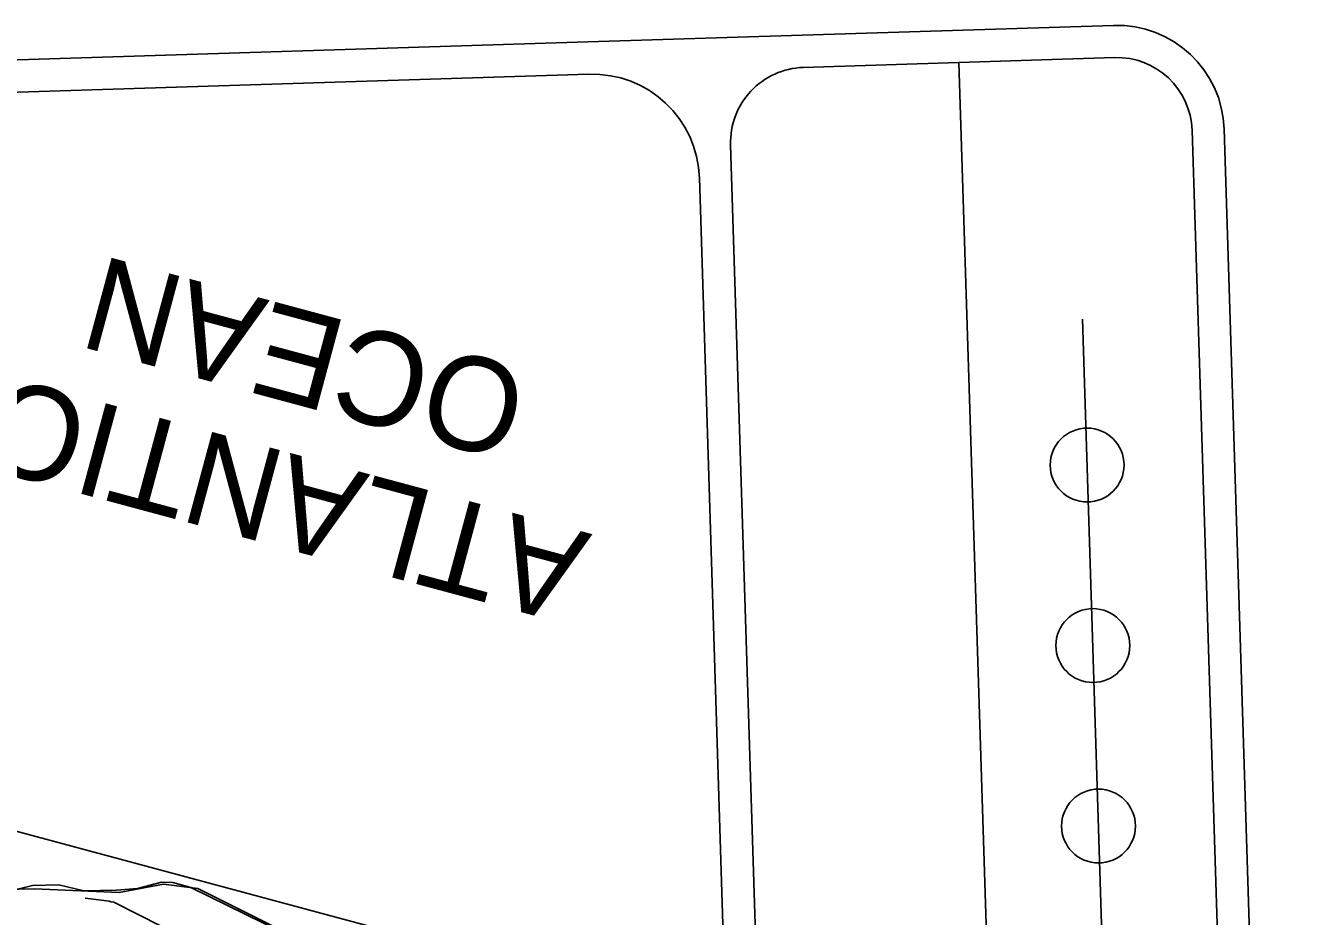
# Model space of a CAD drawing. Extents: x 2308163 to 2335412, y -96774 to 125428.
# Drawn here: x 2326312.3 to 2326608.3, y 123271.9 to 123479.6 of the extents above; entities that cross this region are included whole.
import ezdxf

# ---------------------------------------------------------------- set-up
doc = ezdxf.new("R2010")
doc.units = 0
for name, color, linetype in [('Default', 7, 'Continuous'), ('Old_Level_1', 7, 'Continuous'), ('Old_Level_21', 7, 'Continuous'), ('Old_Level_52', 7, 'Continuous'), ('Old_Level_60', 7, 'Continuous'), ('Old_Level_61', 7, 'Continuous'), ('Old_Level_63', 7, 'Continuous'), ('Prop Horizontal Alignment', 7, 'Continuous')]:
    doc.layers.add(name, color=color, linetype=linetype)

msp = doc.modelspace()

# ---------------------------------------------------------------- linework, layer by layer
at = {"layer": 'Default'}
for centre in [(2326559.69, 123377.11), (2326561.02, 123335.04), (2326562.34, 123292.96)]:
    msp.add_circle(centre, 8.61, dxfattribs=at)
at = {"layer": 'Old_Level_1'}
for p, q in [((2326443.34, 123475.72), (2326493.31, 123477.29)), ((2326493.31, 123477.29), (2326565.85, 123479.58)), ((2325949.48, 123460.16), (2326443.34, 123475.72)), ((2326493.55, 123469.8), (2326566.09, 123472.08)), ((2325949.72, 123452.66), (2326443.57, 123468.22)), ((2326547.56, 122907.89), (2326529.82, 123470.94)), ((2326600.77, 122927.08), (2326584.13, 123455.14)), ((2326493.25, 122923.69), (2326476.61, 123451.75)), ((2326485.52, 122930.95), (2326469.35, 123444.02))]:
    msp.add_line(p, q, dxfattribs=at)
msp.add_lwpolyline([(2326608.27, 122927.31), (2326591.63, 123455.38)], dxfattribs=at)
for centre, radius, start, end in [((2326566.64, 123454.59), 25, 1.8048, 91.8048), ((2326566.64, 123454.59), 17.5, 1.8048, 91.8048), ((2326444.36, 123443.23), 25, 1.8048, 91.8048), ((2326494.1, 123452.3), 17.5, 91.8048, 181.8048)]:
    msp.add_arc(centre, radius, start, end, dxfattribs=at)
at = {"layer": 'Old_Level_52'}
for points in [[(2326352.46, 123278.37), (2326344.49, 123279.39), (2326334.11, 123277.47), (2326314.41, 123278.3), (2326300.12, 123278.02), (2326291.22, 123283.57), (2326287.11, 123292.06), (2326280.06, 123298.67), (2326266.15, 123306.08), (2326194.23, 123339.67), (2326117.56, 123374.58), (2325996.97, 123429.09), (2325967.84, 123440.3), (2325941.49, 123450.31)], [(2326397.87, 123255.63), (2326352.46, 123278.37)]]:
    msp.add_lwpolyline(points, dxfattribs=at)
at = {"layer": 'Old_Level_60'}
msp.add_lwpolyline([(2326302.05, 123273.67), (2326307.94, 123277.66), (2326313.91, 123279.08), (2326320.04, 123279.28), (2326325.92, 123277.85), (2326333.48, 123278), (2326338.39, 123278.44), (2326343.96, 123279.89), (2326346.61, 123279.79), (2326350.86, 123278.63), (2326397.35, 123255.76)], dxfattribs=at)
at = {"layer": 'Old_Level_61'}
msp.add_lwpolyline([(2326397.99, 123248.54), (2326382.78, 123252.63), (2326355.22, 123263.91), (2326332.88, 123275.18), (2326332.2, 123275.27), (2326331.81, 123275.43), (2326326.21, 123276.13)], dxfattribs=at)
at = {"layer": 'Old_Level_63'}
msp.add_lwpolyline([(2326475.8, 123239.36), (2326422.14, 123261.61), (2325934.09, 123392.92)], dxfattribs=at)
at = {"layer": 'Prop Horizontal Alignment'}
msp.add_line((2326558.62, 123411.09), (2326564.74, 123216.9), dxfattribs=at)

# ---------------------------------------------------------------- texts
at = {"layer": 'Old_Level_21'}
for s, height, rotation, p in [('OCEAN', 21.862, 164.9405, (2326430.45, 123399.02)), ('ATLANTIC', 21.862, 164.9405, (2326444.48, 123360.97)), ('Carolina Beach Inlet', 8.8541, 107.8345, (2326321.21, 123209.33))]:
    msp.add_text(s, height=height, rotation=rotation, dxfattribs=at).set_placement(p)

doc.saveas('drawing.dxf')
